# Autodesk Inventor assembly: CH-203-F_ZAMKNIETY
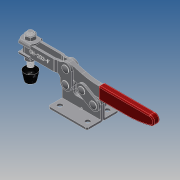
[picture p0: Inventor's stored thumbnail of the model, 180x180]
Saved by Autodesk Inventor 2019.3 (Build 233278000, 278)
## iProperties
Company: Î¢ÈíÖÐ¹ú
Created: 2011-05
Part Number: CH-203-F_ZAMKNIETY
Material: Ogólny
Description: STEP AP203
Document SubType Name: Assembly
Designer: CADENGINEERING4
Sending System: SolidWorks 2010
Preprocessor: SwSTEP 2.0
Title: CH-203-F.STEP
Author: Î¢ÈíÓÃ»§
Revision Number: ÈÎºÎ
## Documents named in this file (10)
- E:\STRONA\Horizontal toggle clamp\CH-203-F\CH-203-F_ZAMKNIETY.iam
- E:\STRONA\Horizontal toggle clamp\CH-203-F\225-D-06.ipt
- E:\STRONA\Horizontal toggle clamp\CH-203-F\203-F-02.ipt
- E:\STRONA\Horizontal toggle clamp\CH-203-F\203-F-04.ipt
- E:\STRONA\Horizontal toggle clamp\CH-203-F\56212-02.ipt
- E:\STRONA\Horizontal toggle clamp\CH-203-F\203-F-03.ipt
- E:\STRONA\Horizontal toggle clamp\CH-203-F\FW516.ipt
- E:\STRONA\Horizontal toggle clamp\CH-203-F\203-F-01.ipt
- E:\STRONA\Horizontal toggle clamp\CH-203-F\203-F-03-02.ipt
- E:\STRONA\Horizontal toggle clamp\CH-203-F\56212.ipt
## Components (15 placed, 15 different names)
1. 225-D-06_1 — Zestawiające:18, Zestawiające:19
2. 225-D-06_2 — Zestawiające:26, Zestawiające:28, Zestawiające:29
3. 203-F-02_3 — Równoległe:1, Zestawiające:5, Zestawiające:7, Zestawiające:9, Zestawiające:25, Zestawiające:26, Zestawiające:27, Zestawiające:29, Zestawiające:30
4. 225-D-06_4 — Zestawiające:20, Zestawiające:22, Zestawiające:23
5. 225-D-06_5 — Zestawiające:13, Zestawiające:30
6. 203-F-04_6 — Zestawiające:14, Zestawiające:16, Zestawiające:18, Zestawiające:19, Zestawiające:21, Zestawiające:22, Zestawiające:23, Zestawiające:24
7. 56212-02_7 — Równoległe:3, Zestawiające:4, Zestawiające:8
8. 203-F-03_8 — Zestawiające:10, Zestawiające:11, Zestawiające:12, Zestawiające:13, Zestawiające:20, Zestawiające:24, Zestawiające:27, Przejściowe:1
9. FW516_9 — Równoległe:2, Zestawiające:1, Zestawiające:5, Zestawiające:6
10. 56212-02_10 — Zestawiające:3, Zestawiające:6
11. 203-F-01_11 — Zestawiające:14, Zestawiające:15, Zestawiające:16, Zestawiające:17, Zestawiające:25, Zestawiające:28, Przejściowe:1
12. 203-F-03-02_12 — Zestawiające:10, Zestawiające:11, Zestawiające:12
13. FW516_13 — Równoległe:1, Równoległe:2, Zestawiające:2, Zestawiające:7, Zestawiające:8
14. 203-F-04_14 — Zestawiające:15, Zestawiające:17, Zestawiające:21
15. 56212_15 — Równoległe:3, Zestawiające:1, Zestawiające:2, Zestawiające:3, Zestawiające:4, Zestawiające:9
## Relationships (34: Mate 30, Flush 3, Transitional 1)
- Równoległe:1 [Flush]: 203-F-02_3 ↔ FW516_13
- Równoległe:2 [Flush]: FW516_9 ↔ FW516_13
- Równoległe:3 [Flush]: 56212-02_7 ↔ 56212_15
- Zestawiające:1 [Mate]: FW516_9 ↔ 56212_15
- Zestawiające:2 [Mate]: FW516_13 ↔ 56212_15
- Zestawiające:3 [Mate]: 56212-02_10 ↔ 56212_15
- Zestawiające:4 [Mate]: 56212-02_7 ↔ 56212_15
- Zestawiające:5 [Mate]: 203-F-02_3 ↔ FW516_9
- Zestawiające:6 [Mate]: FW516_9 ↔ 56212-02_10
- Zestawiające:7 [Mate]: 203-F-02_3 ↔ FW516_13
- Zestawiające:8 [Mate]: 56212-02_7 ↔ FW516_13
- Zestawiające:9 [Mate]: 203-F-02_3 ↔ 56212_15
- Zestawiające:10 [Mate]: 203-F-03_8 ↔ 203-F-03-02_12
- Zestawiające:11 [Mate]: 203-F-03_8 ↔ 203-F-03-02_12
- Zestawiające:12 [Mate]: 203-F-03_8 ↔ 203-F-03-02_12
- Zestawiające:13 [Mate]: 225-D-06_5 ↔ 203-F-03_8
- Zestawiające:14 [Mate]: 203-F-04_6 ↔ 203-F-01_11
- Zestawiające:15 [Mate]: 203-F-01_11 ↔ 203-F-04_14
- Zestawiające:16 [Mate]: 203-F-04_6 ↔ 203-F-01_11
- Zestawiające:17 [Mate]: 203-F-01_11 ↔ 203-F-04_14
- Zestawiające:18 [Mate]: 225-D-06_1 ↔ 203-F-04_6
- Zestawiające:19 [Mate]: 225-D-06_1 ↔ 203-F-04_6
- Zestawiające:20 [Mate]: 225-D-06_4 ↔ 203-F-03_8
- Zestawiające:21 [Mate]: 203-F-04_6 ↔ 203-F-04_14
- Zestawiające:22 [Mate]: 225-D-06_4 ↔ 203-F-04_6
- Zestawiające:23 [Mate]: 225-D-06_4 ↔ 203-F-04_6
- Zestawiające:24 [Mate]: 203-F-04_6 ↔ 203-F-03_8
- Zestawiające:25 [Mate]: 203-F-02_3 ↔ 203-F-01_11
- Zestawiające:26 [Mate]: 225-D-06_2 ↔ 203-F-02_3
- Zestawiające:27 [Mate]: 203-F-02_3 ↔ 203-F-03_8
- Zestawiające:28 [Mate]: 225-D-06_2 ↔ 203-F-01_11
- Zestawiające:29 [Mate]: 225-D-06_2 ↔ 203-F-02_3
- Zestawiające:30 [Mate]: 203-F-02_3 ↔ 225-D-06_5
- Przejściowe:1 [Transitional]: 203-F-03_8 ↔ 203-F-01_11
